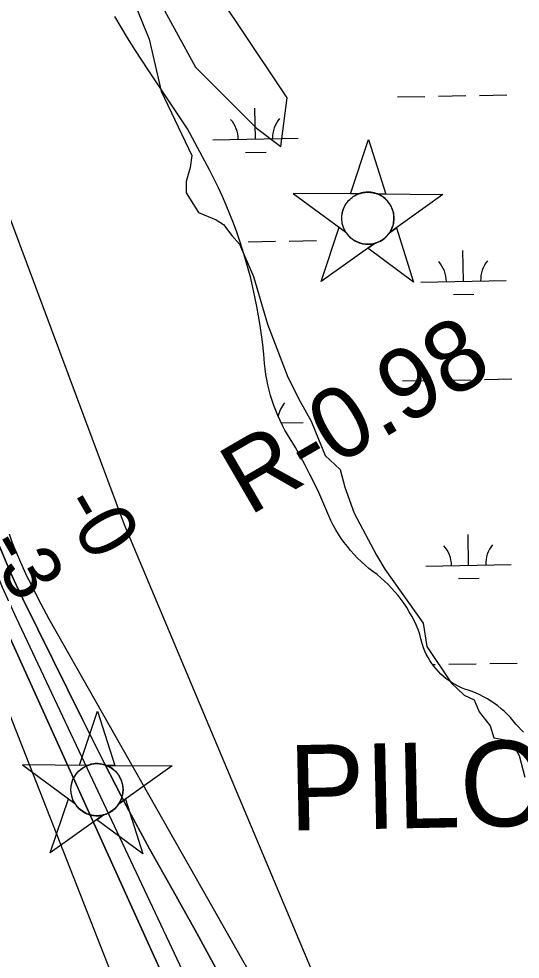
# Model space of a CAD drawing. Extents: x 3914892 to 3953151, y 242587 to 268572.
# Drawn here: x 3944173 to 3944760, y 248739 to 249840 of the extents above; entities that cross this region are included whole.
import ezdxf

# ---------------------------------------------------------------- set-up
doc = ezdxf.new("R2010")
doc.units = 0
for name, color, linetype in [('V-CHAN-NAID', 7, 'Continuous'), ('V-RIVR-EDGE', 7, 'Continuous'), ('V-RIVR-RANG', 7, 'Continuous'), ('V-RIVR-RANG-IDEN', 7, 'Continuous'), ('V-SITE-VEGE', 7, 'Continuous'), ('V-TOPO-DPTH', 7, 'Continuous'), ('V-TOPO-MINR', 7, 'Continuous'), ('V-TOPO-WATR', 7, 'Continuous'), ('V-WETL-SWMP', 7, 'Continuous')]:
    doc.layers.add(name, color=color, linetype=linetype)

msp = doc.modelspace()

# ---------------------------------------------------------------- linework, layer by layer
at = {"layer": 'V-CHAN-NAID'}
for points in [[(3944570.5, 249634.8), (3944560.9, 249634.8), (3944582.1, 249698.3), (3944602.3, 249634.5), (3944592.7, 249634.6), (3944591.1, 249635.2), (3944589, 249635.8), (3944587, 249636.3), (3944585, 249636.6), (3944583.8, 249636.7), (3944582.3, 249636.8), (3944580.5, 249636.8), (3944579.2, 249636.7), (3944577.3, 249636.5), (3944575.9, 249636.3), (3944574.1, 249635.9), (3944572.6, 249635.5), (3944571.5, 249635.1)], [(3944570.5, 249634.8), (3944494, 249635.3), (3944555.6, 249589.9), (3944554.5, 249591.8), (3944553.7, 249593.5), (3944552.9, 249595.4), (3944552.2, 249597.5), (3944551.8, 249598.8), (3944551.4, 249600.4), (3944551.2, 249601.9), (3944551, 249603.5), (3944550.9, 249605.2), (3944550.9, 249606.8), (3944551, 249608.9), (3944551.2, 249610.5), (3944551.6, 249612.7), (3944552, 249614.6), (3944552.6, 249616.5), (3944553.3, 249618.2), (3944554, 249619.8), (3944554.8, 249621.3), (3944555.9, 249623), (3944556.9, 249624.5), (3944557.9, 249625.8), (3944558.9, 249626.9), (3944560.2, 249628.2), (3944561.3, 249629.2), (3944563, 249630.6), (3944564.2, 249631.5), (3944565.9, 249632.6), (3944567.6, 249633.5), (3944569.1, 249634.2)], [(3944592.7, 249634.6), (3944669.2, 249634.1), (3944607, 249589.5), (3944607.9, 249591), (3944608.9, 249592.9), (3944609.6, 249594.5), (3944610.3, 249596.4), (3944610.9, 249598.2), (3944611.3, 249599.8), (3944611.6, 249601.9), (3944611.8, 249603.4), (3944611.9, 249605.6), (3944611.9, 249607.7), (3944611.7, 249609.9), (3944611.5, 249611.7), (3944611, 249613.9), (3944610.3, 249616.1), (3944609.6, 249618), (3944608.9, 249619.5), (3944607.9, 249621.4), (3944606.9, 249623.1), (3944605.7, 249624.8), (3944604.4, 249626.4), (3944603.1, 249627.7), (3944601.5, 249629.3), (3944599.7, 249630.7), (3944598.1, 249631.8), (3944596.2, 249633), (3944594.7, 249633.7)], [(3944589, 249576.6), (3944526.8, 249532.1), (3944547.9, 249595.6), (3944555.6, 249589.9), (3944556.2, 249589), (3944557.6, 249587.1), (3944558.8, 249585.7), (3944560.3, 249584.2), (3944561.7, 249582.9), (3944563.1, 249581.8), (3944564.5, 249580.8), (3944566.2, 249579.7), (3944567.9, 249578.8), (3944569.7, 249578), (3944571.2, 249577.5), (3944572.8, 249576.9), (3944575, 249576.4), (3944576.6, 249576.1), (3944578.6, 249575.8), (3944580.1, 249575.7), (3944582, 249575.7), (3944583.7, 249575.8), (3944585.4, 249576), (3944587.3, 249576.3)], [(3944607, 249589.5), (3944614.8, 249595.1), (3944635, 249531.4), (3944581.2, 249571.1), (3944589, 249576.6), (3944590.6, 249577.1), (3944592.2, 249577.7), (3944594.4, 249578.6), (3944596.1, 249579.5), (3944598, 249580.6), (3944599.7, 249581.8), (3944601.3, 249583), (3944602.6, 249584.2), (3944604, 249585.6), (3944605.2, 249587), (3944606.3, 249588.5)], [(3944253.5, 248965.6), (3944244, 248965.7), (3944265.1, 249029.2), (3944285.3, 248965.4), (3944275.7, 248965.5), (3944274.1, 248966.1), (3944272.1, 248966.7), (3944270, 248967.1), (3944268, 248967.4), (3944266.8, 248967.5), (3944265.3, 248967.6), (3944263.6, 248967.6), (3944262.2, 248967.6), (3944260.3, 248967.4), (3944258.9, 248967.1), (3944257.1, 248966.8), (3944255.6, 248966.3), (3944254.6, 248966)], [(3944253.5, 248965.6), (3944177.1, 248966.2), (3944238.6, 248920.8), (3944237.5, 248922.7), (3944236.7, 248924.3), (3944235.9, 248926.3), (3944235.2, 248928.3), (3944234.8, 248929.7), (3944234.5, 248931.3), (3944234.2, 248932.7), (3944234, 248934.3), (3944233.9, 248936.1), (3944233.9, 248937.6), (3944234, 248939.7), (3944234.2, 248941.3), (3944234.6, 248943.5), (3944235.1, 248945.5), (3944235.7, 248947.4), (3944236.3, 248949), (3944237, 248950.6), (3944237.9, 248952.2), (3944238.9, 248953.9), (3944240, 248955.4), (3944241, 248956.6), (3944242, 248957.8), (3944243.3, 248959.1), (3944244.3, 248960.1), (3944246, 248961.5), (3944247.2, 248962.3), (3944248.9, 248963.4), (3944250.7, 248964.4), (3944252.1, 248965)], [(3944275.7, 248965.5), (3944352.2, 248964.9), (3944290, 248920.4), (3944290.9, 248921.9), (3944291.9, 248923.7), (3944292.6, 248925.3), (3944293.4, 248927.3), (3944293.9, 248929.1), (3944294.3, 248930.7), (3944294.7, 248932.7), (3944294.8, 248934.3), (3944295, 248936.5), (3944294.9, 248938.6), (3944294.8, 248940.8), (3944294.5, 248942.5), (3944294, 248944.8), (3944293.4, 248946.9), (3944292.6, 248948.9), (3944292, 248950.3), (3944291, 248952.3), (3944289.9, 248954), (3944288.7, 248955.7), (3944287.4, 248957.2), (3944286.1, 248958.6), (3944284.5, 248960.1), (3944282.8, 248961.5), (3944281.1, 248962.7), (3944279.2, 248963.8), (3944277.7, 248964.6)], [(3944272, 248907.5), (3944209.8, 248863), (3944230.9, 248926.5), (3944238.6, 248920.8), (3944239.3, 248919.8), (3944240.6, 248918), (3944241.9, 248916.5), (3944243.3, 248915), (3944244.7, 248913.8), (3944246.2, 248912.6), (3944247.6, 248911.6), (3944249.2, 248910.6), (3944251, 248909.7), (3944252.7, 248908.9), (3944254.2, 248908.3), (3944255.8, 248907.8), (3944258, 248907.2), (3944259.6, 248906.9), (3944261.6, 248906.7), (3944263.1, 248906.6), (3944265, 248906.6), (3944266.7, 248906.6), (3944268.4, 248906.8), (3944270.3, 248907.1)], [(3944290, 248920.4), (3944297.8, 248926), (3944318, 248862.2), (3944264.2, 248901.9), (3944272, 248907.5), (3944273.6, 248908), (3944275.3, 248908.5), (3944277.4, 248909.5), (3944279.2, 248910.3), (3944281, 248911.5), (3944282.8, 248912.7), (3944284.3, 248913.9), (3944285.6, 248915.1), (3944287, 248916.5), (3944288.2, 248917.9), (3944289.3, 248919.4)]]:
    msp.add_lwpolyline(points, close=True, dxfattribs=at)
for centre in [(3944581.4, 249606.2), (3944264.4, 248937.1)]:
    msp.add_circle(centre, 30.5, dxfattribs=at)
at = {"layer": 'V-RIVR-EDGE'}
msp.add_lwpolyline([(3944305.7, 249865.1), (3944325.3, 249816), (3944339.5, 249754.9), (3944375.5, 249679.6), (3944373.3, 249665.4), (3944368.9, 249649.1), (3944368.9, 249636), (3944383.1, 249613.1), (3944403.9, 249604.3), (3944412.6, 249598.9), (3944422.4, 249585.8), (3944431.1, 249576), (3944447.5, 249537.8), (3944463.9, 249482.1), (3944487.9, 249420), (3944502, 249391.6), (3944515.1, 249368.7), (3944531.5, 249328.3), (3944548.9, 249312), (3944554.4, 249291.2), (3944565.3, 249260.7), (3944591.5, 249211.6), (3944601.3, 249195.2), (3944646, 249132), (3944650.4, 249104.7), (3944678.8, 249062.1), (3944694, 249047.9), (3944706, 249042.5), (3944711.5, 249028.3), (3944724.6, 249011.9), (3944729, 248997.8), (3944748.6, 248994.5), (3944758.4, 248977), (3944765, 248951.9)], dxfattribs=at)
at = {"layer": 'V-SITE-VEGE'}
msp.add_lwpolyline([(3944336.9, 249861.5), (3944379.7, 249782.9), (3944451.1, 249711.6), (3944479.7, 249690.1), (3944486.8, 249747.2), (3944429.7, 249832.9), (3944386.9, 249897.2)], dxfattribs=at)
at = {"layer": 'V-TOPO-DPTH'}
for points in [[(3944620.8, 248476), (3944296.7, 249247.2), (3943983.6, 250085.5), (3943808.9, 250673.8), (3943732.9, 250836.2), (3943663.5, 251001.9), (3943573.7, 251236.8), (3943554.7, 251287.8), (3943536.4, 251339), (3943519.1, 251390.6), (3943502.4, 251442.4), (3943485.5, 251496.3), (3943477.2, 251521.1), (3943468.2, 251545.7), (3943458.2, 251569.8), (3943447.5, 251593.7), (3943436.2, 251617.3), (3943424.7, 251640.8), (3943412.9, 251664.2), (3943401, 251687.5), (3943105.5, 252257.6)], [(3944379.3, 248472.8), (3944376.2, 248479.8), (3944153.7, 249046.9), (3944143.9, 249072.9), (3944133.6, 249098.6), (3944117.4, 249137.9), (3944114.9, 249143.9), (3944112.4, 249149.9), (3944109.8, 249155.8), (3944107.3, 249161.8), (3943812.4, 249910)], [(3944379.3, 248472.8), (3944376.2, 248479.8), (3944153.7, 249046.9), (3944143.9, 249072.9), (3944133.6, 249098.6), (3944117.4, 249137.9), (3944114.9, 249143.9), (3944112.4, 249149.9), (3944109.8, 249155.8), (3944107.3, 249161.8), (3943812.4, 249910)], [(3944446.4, 248474.1), (3944444.3, 248478.9), (3944439.2, 248490.7), (3944427.9, 248517.2), (3944417.2, 248542.3), (3944406.5, 248567.3), (3944396, 248592.4), (3944385.4, 248617.6), (3944382, 248625.7), (3944369.6, 248654.9), (3944357.1, 248683.9), (3944344.4, 248712.9), (3944331.4, 248741.8), (3944162.6, 249115.4), (3944151.3, 249140.6), (3944140.1, 249165.9), (3944129.1, 249191.3), (3944118.2, 249216.8), (3943880.1, 249911.6)], [(3943880.1, 249911.6), (3944118.2, 249216.8), (3944129.1, 249191.3), (3944140.1, 249165.9), (3944151.3, 249140.6), (3944162.6, 249115.4), (3944331.4, 248741.8), (3944344.4, 248712.9), (3944357.1, 248683.9), (3944369.6, 248654.9), (3944382, 248625.7), (3944385.4, 248617.6), (3944396, 248592.4), (3944406.5, 248567.3), (3944417.2, 248542.3), (3944427.9, 248517.2), (3944439.2, 248490.7), (3944444.3, 248478.9), (3944446.4, 248474.1)], [(3943925.3, 249896.6), (3944120, 249294.3), (3944127.4, 249275.7), (3944158, 249203.5), (3944162.7, 249192.7), (3944167.5, 249181.9), (3944172.5, 249171.2), (3944177.7, 249160.5), (3944247.7, 249018.4), (3944273.1, 248967.9), (3944299.1, 248917.7), (3944326, 248868), (3944353.5, 248818.6), (3944381.1, 248769.3), (3944408.3, 248719.7), (3944434.8, 248669.8), (3944460.9, 248619.7), (3944534.7, 248475.7), (3944446.4, 248474.1)], [(3943925.3, 249896.6), (3944120, 249294.3), (3944127.4, 249275.7), (3944158, 249203.5), (3944162.7, 249192.7), (3944167.5, 249181.9), (3944172.5, 249171.2), (3944177.7, 249160.5), (3944247.7, 249018.4), (3944273.1, 248967.9), (3944299.1, 248917.7), (3944326, 248868), (3944353.5, 248818.6), (3944381.1, 248769.3), (3944408.3, 248719.7), (3944434.8, 248669.8), (3944460.9, 248619.7), (3944534.7, 248475.7)]]:
    msp.add_lwpolyline(points, dxfattribs=at)
at = {"layer": 'V-TOPO-MINR'}
for points in [[(3944582.9, 248476.5), (3944208.6, 249136.7), (3944199.2, 249154.2), (3944184.5, 249182.8), (3944182.8, 249186.3), (3944181.1, 249189.8), (3944179.4, 249193.3), (3944177.9, 249196.9), (3944167.6, 249221.2), (3944165.3, 249227.1), (3943931.5, 249926)], [(3944379.3, 248472.8), (3944376.2, 248479.8), (3944153.7, 249046.9), (3944143.9, 249072.9), (3944133.6, 249098.6), (3944117.4, 249137.9), (3944114.9, 249143.9), (3944112.4, 249149.9), (3944109.8, 249155.8), (3944107.3, 249161.8), (3943812.4, 249910)], [(3944446.4, 248474.1), (3944444.3, 248478.9), (3944439.2, 248490.7), (3944427.9, 248517.2), (3944417.2, 248542.3), (3944406.5, 248567.3), (3944396, 248592.4), (3944385.4, 248617.6), (3944382, 248625.7), (3944369.6, 248654.9), (3944357.1, 248683.9), (3944344.4, 248712.9), (3944331.4, 248741.8), (3944162.6, 249115.4), (3944151.3, 249140.6), (3944140.1, 249165.9), (3944129.1, 249191.3), (3944118.2, 249216.8), (3943880.1, 249911.6)], [(3944486.5, 248474.8), (3944475.8, 248495.8), (3944467.3, 248512.5), (3944458.8, 248529.2), (3944450.3, 248545.9), (3944441.9, 248562.7), (3944433.6, 248579.5), (3944425.4, 248596.3), (3944417.3, 248613.2), (3944409.2, 248630.2), (3944170.3, 249138), (3944162, 249156), (3944153.9, 249173.9), (3944145.9, 249192), (3943903, 249904)], [(3944534.7, 248475.7), (3944460.9, 248619.7), (3944434.8, 248669.8), (3944408.3, 248719.7), (3944381.1, 248769.3), (3944353.5, 248818.6), (3944326, 248868), (3944299.1, 248917.7), (3944273.1, 248967.9), (3944247.7, 249018.4), (3944177.7, 249160.5), (3944172.5, 249171.2), (3944167.5, 249181.9), (3944162.7, 249192.7), (3944158, 249203.5), (3944127.4, 249275.7), (3944120, 249294.3), (3943925.3, 249896.6)]]:
    msp.add_lwpolyline(points, dxfattribs=at)
at = {"layer": 'V-TOPO-WATR'}
msp.add_lwpolyline([(3944620.8, 248476), (3944296.7, 249247.2), (3943983.6, 250085.5), (3943808.9, 250673.8), (3943732.9, 250836.2), (3943663.5, 251001.9), (3943573.7, 251236.8), (3943554.7, 251287.8), (3943536.4, 251339), (3943519.1, 251390.6), (3943502.4, 251442.4), (3943485.5, 251496.3), (3943477.2, 251521.1), (3943468.2, 251545.7), (3943458.2, 251569.8), (3943447.5, 251593.7), (3943436.2, 251617.3), (3943424.7, 251640.8), (3943412.9, 251664.2), (3943401, 251687.5), (3943105.5, 252257.6)], dxfattribs=at)
at = {"layer": 'V-WETL-SWMP'}
for p, q in [((3944300.3, 249817.5), (3944285.4, 249842.3)), ((3944309.4, 249802.5), (3944300.3, 249817.5)), ((3944324.2, 249779.9), (3944309.4, 249802.5)), ((3944353.8, 249735.6), (3944324.2, 249779.9)), ((3944616.1, 249748.3), (3944648.1, 249748.9)), ((3944664.1, 249749.2), (3944696.1, 249749.7)), ((3944712.1, 249750), (3944744.1, 249750.6)), ((3944370.5, 249711), (3944353.8, 249735.6)), ((3944449.9, 249698.9), (3944449.2, 249734.9)), ((3944396.5, 249662.1), (3944370.5, 249711)), ((3944399.9, 249698), (3944499.9, 249699.8)), ((3944438.2, 249683.3), (3944462.2, 249683.7)), ((3944401.6, 249652), (3944396.5, 249662.1)), ((3944406.5, 249641.9), (3944401.6, 249652)), ((3944411.1, 249631.6), (3944406.5, 249641.9)), ((3944415.6, 249621.3), (3944411.1, 249631.6)), ((3944419.9, 249610.9), (3944415.6, 249621.3)), ((3944424, 249600.4), (3944419.9, 249610.9)), ((3944427.9, 249589.8), (3944424, 249600.4)), ((3944431.6, 249579.2), (3944427.9, 249589.8)), ((3944435.1, 249568.5), (3944431.6, 249579.2)), ((3944441.2, 249578.7), (3944473.2, 249579.2)), ((3944489.2, 249579.5), (3944521.2, 249580.1)), ((3944438.3, 249557.7), (3944435.1, 249568.5)), ((3944693.4, 249532.4), (3944692.7, 249568.4)), ((3944441.4, 249546.8), (3944438.3, 249557.7)), ((3944444.3, 249535.9), (3944441.4, 249546.8)), ((3944446.9, 249525), (3944444.3, 249535.9)), ((3944643.4, 249531.5), (3944743.4, 249533.3)), ((3944449.3, 249514), (3944446.9, 249525)), ((3944451.6, 249502.9), (3944449.3, 249514)), ((3944681.6, 249516.8), (3944705.6, 249517.2)), ((3944453.6, 249491.9), (3944451.6, 249502.9)), ((3944455.4, 249480.7), (3944453.6, 249491.9)), ((3944457, 249469.6), (3944455.4, 249480.7)), ((3944458.3, 249458.4), (3944457, 249469.6)), ((3944459.5, 249447.2), (3944458.3, 249458.4)), ((3944460.4, 249436), (3944459.5, 249447.2)), ((3944461.1, 249429.7), (3944460.4, 249436)), ((3944462, 249423.4), (3944461.1, 249429.7)), ((3944463.1, 249417.2), (3944462, 249423.4)), ((3944464.3, 249411), (3944463.1, 249417.2)), ((3944465.8, 249404.9), (3944464.3, 249411)), ((3944622, 249415.7), (3944654, 249416.3)), ((3944670, 249416.6), (3944702, 249417.1)), ((3944718, 249417.4), (3944750, 249418)), ((3944467.5, 249398.8), (3944465.8, 249404.9)), ((3944469.3, 249392.8), (3944467.5, 249398.8)), ((3944471.4, 249386.8), (3944469.3, 249392.8)), ((3944473.6, 249380.9), (3944471.4, 249386.8)), ((3944476, 249375.1), (3944473.6, 249380.9)), ((3944478.6, 249369.3), (3944476, 249375.1)), ((3944481.4, 249363.7), (3944478.6, 249369.3)), ((3944479.9, 249366.7), (3944505.8, 249367.2)), ((3944484.4, 249358.1), (3944481.4, 249363.7)), ((3944490.6, 249348), (3944484.4, 249358.1)), ((3944496.7, 249337.7), (3944490.6, 249348)), ((3944502.5, 249327.4), (3944496.7, 249337.7)), ((3944508.1, 249316.9), (3944502.5, 249327.4)), ((3944513.6, 249306.3), (3944508.1, 249316.9)), ((3944518.8, 249295.7), (3944513.6, 249306.3)), ((3944523.9, 249284.9), (3944518.8, 249295.7)), ((3944528.7, 249274), (3944523.9, 249284.9)), ((3944533.3, 249263.1), (3944528.7, 249274)), ((3944535.7, 249257.6), (3944533.3, 249263.1)), ((3944538.2, 249252.1), (3944535.7, 249257.6)), ((3944540.9, 249246.8), (3944538.2, 249252.1)), ((3944543.8, 249241.5), (3944540.9, 249246.8)), ((3944547, 249236.4), (3944543.8, 249241.5)), ((3944550.3, 249231.4), (3944547, 249236.4)), ((3944553.7, 249226.5), (3944550.3, 249231.4)), ((3944699.3, 249199.8), (3944698.7, 249235.8)), ((3944557.4, 249221.7), (3944553.7, 249226.5)), ((3944561.2, 249217.1), (3944557.4, 249221.7)), ((3944565.2, 249212.6), (3944561.2, 249217.1)), ((3944569.3, 249208.3), (3944565.2, 249212.6)), ((3944573.6, 249204.1), (3944569.3, 249208.3)), ((3944578.1, 249200.1), (3944573.6, 249204.1)), ((3944582.7, 249196.2), (3944578.1, 249200.1)), ((3944649.3, 249198.9), (3944749.3, 249200.7)), ((3944587.4, 249192.5), (3944582.7, 249196.2)), ((3944592.3, 249189), (3944587.4, 249192.5)), ((3944596.7, 249185.3), (3944592.3, 249189)), ((3944601, 249181.4), (3944596.7, 249185.3)), ((3944605.2, 249177.4), (3944601, 249181.4)), ((3944609.2, 249173.2), (3944605.2, 249177.4)), ((3944687.6, 249184.2), (3944711.6, 249184.6)), ((3944613.1, 249168.9), (3944609.2, 249173.2)), ((3944616.8, 249164.4), (3944613.1, 249168.9)), ((3944620.3, 249159.8), (3944616.8, 249164.4)), ((3944623.7, 249155.1), (3944620.3, 249159.8)), ((3944626.9, 249150.3), (3944623.7, 249155.1)), ((3944629.9, 249145.4), (3944626.9, 249150.3)), ((3944632.8, 249140.3), (3944629.9, 249145.4)), ((3944635.5, 249135.2), (3944632.8, 249140.3)), ((3944638, 249130), (3944635.5, 249135.2)), ((3944640.3, 249124.7), (3944638, 249130)), ((3944642.4, 249119.3), (3944640.3, 249124.7)), ((3944643.1, 249115.2), (3944642.4, 249119.3)), ((3944644.1, 249111.2), (3944643.1, 249115.2)), ((3944645.2, 249107.2), (3944644.1, 249111.2)), ((3944646.6, 249103.3), (3944645.2, 249107.2)), ((3944648.1, 249099.4), (3944646.6, 249103.3)), ((3944649.8, 249095.7), (3944648.1, 249099.4)), ((3944651.8, 249092), (3944649.8, 249095.7)), ((3944653.9, 249088.5), (3944651.8, 249092)), ((3944656.1, 249085), (3944653.9, 249088.5)), ((3944658.6, 249081.7), (3944656.1, 249085)), ((3944657.2, 249083.6), (3944660, 249083.6)), ((3944661.2, 249078.5), (3944658.6, 249081.7)), ((3944664, 249075.4), (3944661.2, 249078.5)), ((3944676, 249083.9), (3944708, 249084.5)), ((3944724, 249084.8), (3944756, 249085.4)), ((3944666.9, 249072.4), (3944664, 249075.4)), ((3944670, 249069.7), (3944666.9, 249072.4)), ((3944673.2, 249067), (3944670, 249069.7)), ((3944676.5, 249064.6), (3944673.2, 249067)), ((3944679.9, 249062.3), (3944676.5, 249064.6)), ((3944683.5, 249060.2), (3944679.9, 249062.3)), ((3944687.2, 249058.2), (3944683.5, 249060.2)), ((3944690.9, 249056.5), (3944687.2, 249058.2)), ((3944694.7, 249054.9), (3944690.9, 249056.5)), ((3944698.6, 249053.6), (3944694.7, 249054.9)), ((3944703.3, 249051.9), (3944698.6, 249053.6)), ((3944708, 249050.1), (3944703.3, 249051.9)), ((3944712.5, 249048), (3944708, 249050.1)), ((3944716.9, 249045.8), (3944712.5, 249048)), ((3944721.3, 249043.4), (3944716.9, 249045.8)), ((3944725.5, 249040.8), (3944721.3, 249043.4)), ((3944729.7, 249038), (3944725.5, 249040.8)), ((3944733.7, 249035.1), (3944729.7, 249038)), ((3944737.5, 249031.9), (3944733.7, 249035.1)), ((3944741.3, 249028.7), (3944737.5, 249031.9)), ((3944744.9, 249025.2), (3944741.3, 249028.7)), ((3944748.3, 249021.6), (3944744.9, 249025.2)), ((3944751.6, 249017.9), (3944748.3, 249021.6)), ((3944754.7, 249014), (3944751.6, 249017.9)), ((3944763.4, 249004.5), (3944754.7, 249014))]:
    msp.add_line(p, q, dxfattribs=at)
for centre, start, end in [((3944394.6, 249698.4), 0.2532, 41.7968), ((3944505.1, 249700.4), 140.2532, 181.7968), ((3944638.1, 249531.9), 0.2532, 41.7968), ((3944748.6, 249533.9), 140.2532, 181.7968), ((3944511.1, 249367.7), 140.2532, 169.3766), ((3944644.1, 249199.3), 0.2532, 41.7968), ((3944754.5, 249201.3), 140.2532, 181.7968)]:
    msp.add_arc(centre, 35.2, start, end, dxfattribs=at)

# ---------------------------------------------------------------- texts
at = {"layer": 'V-CHAN-NAID'}
msp.add_text('PILOTTOWN RANGE A FRONT (1.0)', height=100, rotation=1.1731, dxfattribs=at).set_placement((3944489.6, 248889.1))
at = {"layer": 'V-RIVR-RANG'}
for s, p in [('-0', (3944220, 249270.5)), ('-3', (3944132.4, 249222.3))]:
    msp.add_text(s, height=67, rotation=300.0283, dxfattribs=at).set_placement(p)
at = {"layer": 'V-RIVR-RANG-IDEN'}
msp.add_text('R-0.98', height=83, rotation=30.172, dxfattribs=at).set_placement((3944442.5, 249257.1))

doc.saveas('drawing.dxf')
